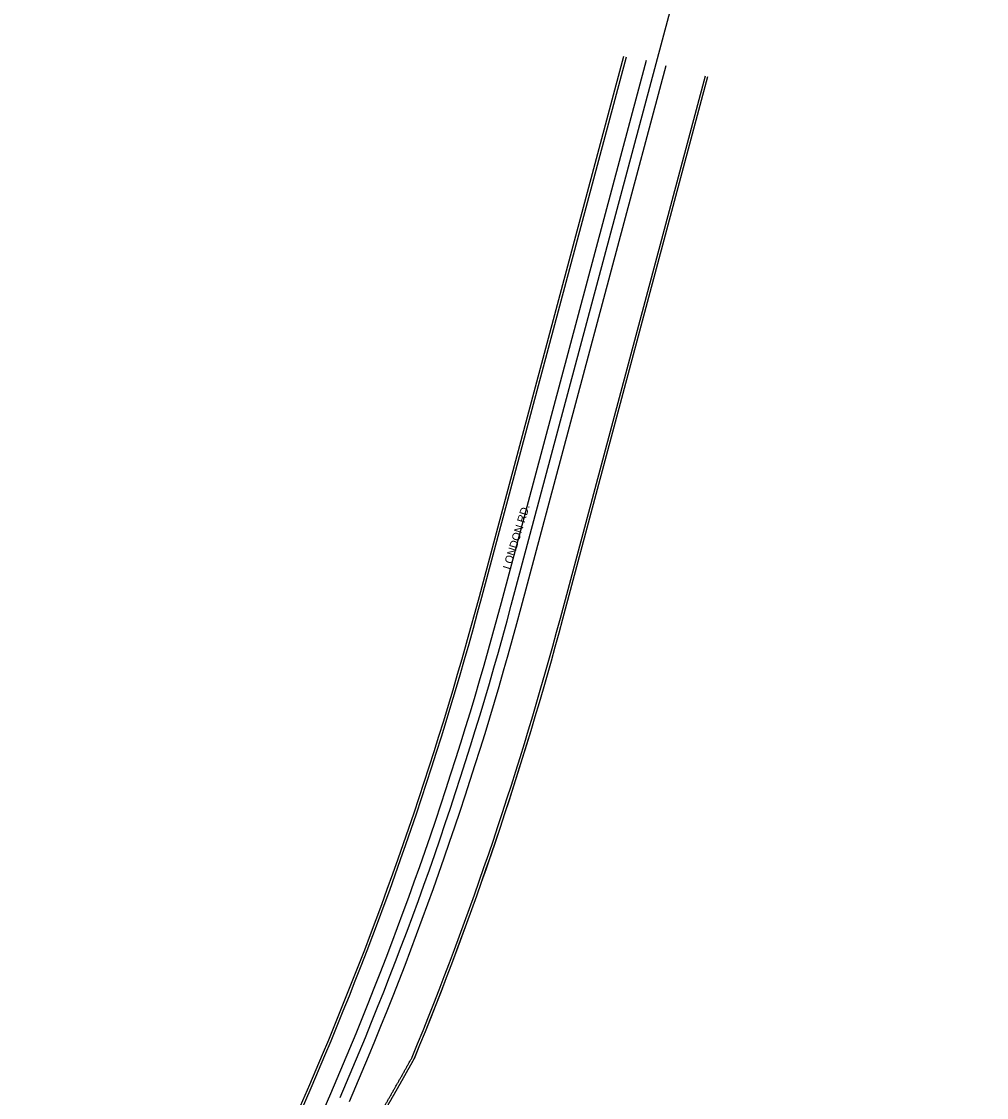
# Model space of a CAD drawing. Extents: x 2315515 to 2326910, y 758186 to 762794.
# Drawn here: x 2321348 to 2321918, y 761455 to 762090 of the extents above; entities that cross this region are included whole.
import ezdxf

# ---------------------------------------------------------------- set-up
doc = ezdxf.new("R2010")
doc.units = 0
for name, color, linetype in [('Default', 7, 'Continuous'), ('E_Terrain_Exterior', 7, 'Continuous'), ('Pavement Marking Yellow', 7, 'Continuous'), ('Road_Curb_Face', 7, 'Continuous')]:
    doc.layers.add(name, color=color, linetype=linetype)

msp = doc.modelspace()

# ---------------------------------------------------------------- linework, layer by layer
at = {"layer": 'Default'}
msp.add_line((2321637.04, 761745.17), (2321917.56, 762793.58), dxfattribs=at)
msp.add_line((2321637.04, 761745.17), (2321917.56, 762793.58), dxfattribs=at)
msp.add_line((2321637.04, 761745.17), (2321917.56, 762793.58), dxfattribs=at)
msp.add_arc((2319608.41, 762287.97), 2100, 336.61697, 345.02036, dxfattribs=at)
msp.add_arc((2319608.41, 762287.97), 2100, 336.61697, 345.02036, dxfattribs=at)
msp.add_arc((2319608.41, 762287.97), 2100, 336.61697, 345.02036, dxfattribs=at)
at = {"layer": 'E_Terrain_Exterior'}
for p, q in [((2321619.65, 761749.83), (2321704.98, 762068.71)), ((2321619.65, 761749.83), (2321704.98, 762068.71)), ((2321666.02, 761737.42), (2321751.64, 762057.38)), ((2321666.02, 761737.42), (2321751.64, 762057.38)), ((2321351.39, 761073.08), (2321519.42, 761461.68)), ((2321351.39, 761073.08), (2321519.42, 761461.68))]:
    msp.add_line(p, q, dxfattribs=at)
for radius, start in [(2082, 336.61697), (2082, 336.61697), (2130, 337.65654), (2130, 337.65654)]:
    msp.add_arc((2319608.41, 762287.97), radius, start, 345.02036, dxfattribs=at)
msp.add_open_spline([(2321559.28, 761444.44), (2321559.6, 761445), (2321560.25, 761446.12), (2321561.22, 761447.8), (2321562.2, 761449.48), (2321563.17, 761451.17), (2321564.13, 761452.85), (2321565.1, 761454.54), (2321566.07, 761456.22), (2321567.03, 761457.91), (2321567.99, 761459.6), (2321568.96, 761461.29), (2321569.92, 761462.98), (2321570.87, 761464.67), (2321571.83, 761466.36), (2321572.79, 761468.05), (2321573.74, 761469.75), (2321574.69, 761471.44), (2321575.64, 761473.14), (2321576.59, 761474.84), (2321577.54, 761476.54), (2321578.17, 761477.67), (2321578.49, 761478.24)], degree=3, dxfattribs=at)
msp.add_open_spline([(2321559.28, 761444.44), (2321559.6, 761445), (2321560.25, 761446.12), (2321561.22, 761447.8), (2321562.2, 761449.48), (2321563.17, 761451.17), (2321564.13, 761452.85), (2321565.1, 761454.54), (2321566.07, 761456.22), (2321567.03, 761457.91), (2321567.99, 761459.6), (2321568.96, 761461.29), (2321569.92, 761462.98), (2321570.87, 761464.67), (2321571.83, 761466.36), (2321572.79, 761468.05), (2321573.74, 761469.75), (2321574.69, 761471.44), (2321575.64, 761473.14), (2321576.59, 761474.84), (2321577.54, 761476.54), (2321578.17, 761477.67), (2321578.49, 761478.24)], degree=3, dxfattribs=at)
at = {"layer": 'Pavement Marking Yellow'}
for p, q in [((2321631.25, 761746.73), (2321716.86, 762066.69)), ((2321642.84, 761743.62), (2321728.45, 762063.59)), ((2321347.87, 761034.71), (2321530.43, 761456.92))]:
    msp.add_line(p, q, dxfattribs=at)
for radius in [2094, 2106]:
    msp.add_arc((2319608.41, 762287.97), radius, 336.61697, 345.02036, dxfattribs=at)
at = {"layer": 'Road_Curb_Face'}
for p, q in [((2321618.21, 761750.21), (2321703.53, 762069.1)), ((2321667.47, 761737.03), (2321753.08, 762056.99)), ((2321667.47, 761737.03), (2321753.08, 762056.99)), ((2321579.8, 761477.51), (2321579.84, 761477.59)), ((2321350.01, 761073.67), (2321518.04, 761462.27))]:
    msp.add_line(p, q, dxfattribs=at)
for radius, start in [(2080.5, 336.61697), (2131.5, 337.65416), (2131.5, 337.65654)]:
    msp.add_arc((2319608.41, 762287.97), radius, start, 345.02036, dxfattribs=at)
msp.add_open_spline([(2321560.57, 761443.69), (2321560.76, 761444.01), (2321561.4, 761445.11), (2321562.57, 761447.12), (2321563.49, 761448.72), (2321564.47, 761450.43), (2321565.44, 761452.11), (2321566.41, 761453.8), (2321567.37, 761455.49), (2321568.34, 761457.17), (2321569.3, 761458.86), (2321570.27, 761460.55), (2321571.23, 761462.25), (2321572.18, 761463.94), (2321573.14, 761465.63), (2321574.1, 761467.32), (2321575.05, 761469.02), (2321576, 761470.71), (2321576.97, 761472.43), (2321577.87, 761474.04), (2321579, 761476.07), (2321579.62, 761477.19), (2321579.8, 761477.51)], degree=2, dxfattribs=at)
msp.add_open_spline([(2321560.57, 761443.69), (2321560.76, 761444.01), (2321561.4, 761445.11), (2321562.57, 761447.12), (2321563.49, 761448.72), (2321564.47, 761450.43), (2321565.44, 761452.11), (2321566.41, 761453.8), (2321567.37, 761455.49), (2321568.34, 761457.17), (2321569.3, 761458.86), (2321570.27, 761460.55), (2321571.23, 761462.25), (2321572.18, 761463.94), (2321573.14, 761465.63), (2321574.1, 761467.32), (2321575.05, 761469.02), (2321576, 761470.71), (2321576.97, 761472.43), (2321577.87, 761474.04), (2321579, 761476.07), (2321579.62, 761477.19), (2321579.8, 761477.51)], degree=2, dxfattribs=at)

# ---------------------------------------------------------------- texts
at = {"layer": 'Default'}
msp.add_text('LONDON RD.', height=4.724, rotation=73.03428, dxfattribs=at).set_placement((2321636.42, 761765.77))

doc.saveas('drawing.dxf')
